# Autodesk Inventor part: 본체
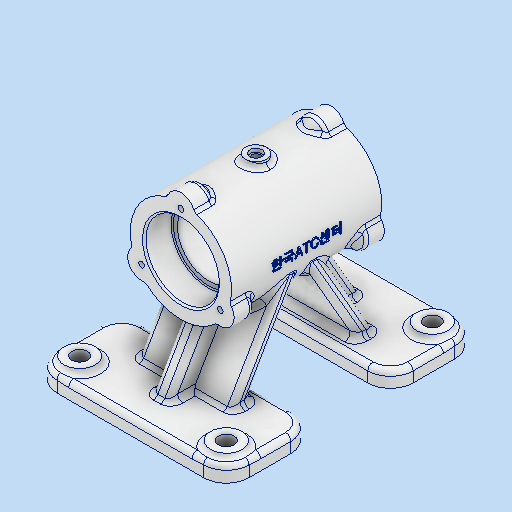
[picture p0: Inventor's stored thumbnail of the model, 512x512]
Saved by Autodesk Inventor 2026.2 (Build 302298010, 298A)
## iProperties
Created: 2026-04
Part Number: 본체
Material: 알루미늄 6061
Document SubType Name: Modeling
Designer: PC-2-06
Mass: 746.295 g
Surface Area: 674.064 cm^2
Volume: 276.405 cm^3
Density: 2.7 g/cm^3
Appearance: 알루미늄 - 평지
Author: PC-2-06
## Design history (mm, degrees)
sketch "스케치1"
  geometry: C1 r 29 at (0, 0); 1 further point
  constraints: 1 centre point, 1 coincident
  dimensions: "d0" = 58 diameter of C1
extrude "돌출1" new body sketch "스케치1" stored distance "d1" = 86; taper "d2" = 0 deg
sketch "스케치2" dims "d3" = 52
  geometry: L1 (0, 41.8)-(0, -40.8) reference; L2 (-40.6, 0)-(40.6, 0) reference; C1 r 8 at (0, 26); C2 r 8 at (-22.517, -13); C3 r 8 at (22.517, -13); 2 further points
  constraints: 3 centre point, 1 coincident, 1 point on line, 1 vertical alignment, 9 other
  dimensions: "d4" = 16 diameter of C1; "d7" = 360 deg dimension on point (0, 0) C1.centre (derived)
extrude "돌출2" join sketch "스케치2" distance "d9" = 10; taper "d10" = 0 deg
sketch "스케치3" dims "d11" = 52
  geometry: L1 (-42.723, 0)-(42.723, 0) reference; L2 (0, -41.6)-(0, 46.6) reference; 5 further points
  constraints: 1 coincident, 1 point on line, 1 vertical alignment, 6 other
  dimensions: "d14" = 360 deg dimension on point (0, 0) point (0, 26) (derived)
hole "구멍1" sketch "스케치3" at (0, 26), (-22.517, -13), (22.517, -13) diameter "d16" = 3.242; stored, may be unused: countersink angle "d20" = 90 deg, drill point angle "d22" = 118 deg; dims "d17" = 8, "d18" = 4, "d19" = 2, "d21" = 10
node "작업 평면1"
sketch "스케치4"
  geometry: L1 (55, 72)-(-55, 72); L2 (-55, 72)-(-55, 22); L3 (-55, 22)-(55, 22); L4 (55, 22)-(55, 72); L5 (55, -22)-(-55, -22); L6 (-55, -22)-(-55, -72); L7 (-55, -72)-(55, -72); L8 (55, -72)-(55, -22); L9 (0, -127.783)-(0, 129.949) reference; L10 (-81.651, 0)-(69.198, 0) reference; 1 further point
  constraints: 16 end point, 4 parallel, 2 horizontal, 2 perpendicular, 1 point on line, 3 other
  dimensions: "d24" = 144 distance between parallel lines of L7 L1; "d25" = 110 distance of L1.start L1.end; "d26" = 50 distance of L3.end L1.start; "d27" = 44 distance of L5.end L2.end
extrude "돌출3" join sketch "스케치4" distance "d28" = 9; taper "d29" = 0 deg
fillet "모깎기1" dims "d30" = 13
sketch "스케치5"
  geometry: C1 r 9 at (-42, -59); C2 r 9 at (42, -59); A1 r 13 centre (-42, -59) between (-55, -59) and (-42, -72) reference; A2 r 13 centre (42, -59) between (42, -72) and (55, -59) reference; 1 further point
  constraints: 2 centre point, 2 coincident
  dimensions: "d31" = 18 diameter of C1; "d33" = 18 diameter of C2
extrude "돌출5" join sketch "스케치5" distance "d41" = 3; taper "d42" = 0 deg
sketch "스케치7"
  geometry: C1 r 9 at (0, 0) reference; C2 r 9 at (84, 0) reference; C3 r 4.5 at (0, 0); C4 r 4.5 at (84, 0); 1 further point
  constraints: 2 centre point, 2 coincident
  dimensions: "d43" = 9 diameter of C3; "d44" = 9 diameter of C4
extrude "돌출6" cut sketch "스케치7" extent not by distance; stored distance "d45" = 0; taper "d46" = 0 deg
sketch "스케치8"
  geometry: L1 (-29, -43)-(-29, 43) reference; L2 (27.942, 43)-(-7.25, 43) reference; L3 (-72, 59)-(-72, 35) reference; L4 (-72, 22)-(-72, 35) reference; L5 (-63, 35)-(-63, 22) reference; L6 (-63, 59)-(-63, 35) reference; L7 (-63, -59)-(-63, -35) reference; L8 (-63, -22)-(-63, -35) reference; L9 (-60, -50)-(-60, -68) reference; L10 (-63, -50)-(-63, -68) reference; L11 (-72, -59)-(-72, -35) reference; L12 (-72, -22)-(-63, -22) reference; L13 (-63, 32)-(-7.574, 0); L14 (-7.574, 0)-(-63, -32); L15 (-93.2, 0)-(55.2, 0) reference; L16 (-67.431, 43.796)-(0, 4.865); L17 (0, -4.865)-(-67.337, -43.742); L18 (0, 100.8)-(0, -100.8) reference; L19 (0, 4.865)-(0, -4.865); 3 further points
  constraints: 10 end point, 5 point on line, 2 parallel, 1 collinear, 1 other
  dimensions: "d48" = 10 distance of L5.end L13.start; "d49" = 60 deg angle of L14 L13; "d50" = 8 distance between parallel lines of L13 L16; "d51" = 8 distance between parallel lines of L14 L17
extrude "돌출7" join sketch "스케치8" stored distance "d52" = 54; taper "d53" = 0 deg
sketch "스케치9"
  geometry: L1 (-10.583, 10.975)-(-63, 41.238) reference; L2 (-10.583, -10.975)-(-63, -41.238) reference; L3 (-10.583, 1.737)-(-63, 32) reference; L4 (0, 18.721)-(-63, 55.094); L5 (-63, 68)-(-63, 50) reference; L6 (-63, 35)-(-63, 59) reference; L7 (0, 4.865)-(-63, 41.238); L8 (0, 100.8)-(0, -100.8) reference; 2 further points
  constraints: 4 end point, 4 point on line, 2 parallel
  dimensions: "d54" = 12 distance between parallel lines of L1 L4; "d55" = 12 distance between parallel lines of L4 L7
extrude "돌출8" join sketch "스케치9" stored distance "d56" = 10; taper "d57" = 0 deg
sketch "스케치10"
  geometry: L1 (0, 100.8)-(0, -100.8) reference; L2 (-93.2, 0)-(55.2, 0) reference; L3 (0, 43)-(21, 43); L4 (21, 43)-(21, 27.6); L5 (20.4, 27)-(0, 27); L6 (0, 27)-(0, 43); L7 (27.942, 43)-(-7.25, 43) reference; L8 (0, 27)-(18, 27); L9 (18, 27)-(18, -27); L10 (18, -27)-(0, -27); L11 (0, -27)-(0, 27); L12 (0, -43)-(21, -43); L13 (21, -43)-(21, -27.6); L14 (20.4, -27)-(0, -27); A1 r 0.6 centre (20.4, 27.6) between (20.4, 27) and (21, 27.6); A2 r 0.6 centre (20.4, -27.6) between (21, -27.6) and (20.4, -27); 6 further points
  constraints: 22 end point, 6 point on line, 4 parallel, 4 point on circle, 4 tangent, 3 symmetric about line, 2 centre point, 2 horizontal, 2 perpendicular, 1 equal radius
  dimensions: "d58" = 21 distance of point (21, 27) L5.end; "d59" = 16 distance of L3.end point (21, 27); "d60" = 18 distance of L9.end L10.end; "d61" = 54 distance of L8.end L9.end; "d62" = 0.6 radius of A1 (derived)
revolve "회전1" sketch "스케치10" stored, may be unused: angle "d63" = 90 deg
chamfer "모따기1" distance "d64" = 1; stored, may be unused: second distance "d65" = 2, angle "d66" = 45 deg
sketch "스케치11"
  geometry: L1 (34, 33)-(1, 0); L2 (1, 0)-(34, -33); L3 (0, 100.8)-(0, -100.8) reference; L4 (-98.48, 0)-(86.879, 0) reference; L5 (27.942, 33)-(34, 33) reference; L6 (34, 43)-(34, 33) reference; L7 (27.942, -33)-(34, -33) reference; L8 (34, -33)-(34, -43) reference; L9 (24.379, 43)-(27.621, 43) reference; L10 (26, 43)-(26, -43); L11 (27.621, -43)-(24.379, -43) reference; L12 (34, -33)-(26, -33); L13 (34, 33)-(26, 33); 5 further points
  constraints: 10 end point, 4 point on line, 2 midpoint, 1 perpendicular, 1 other
  dimensions: "d67" = 90 deg angle of L2 L1
revolve "회전2" sketch "스케치11" stored, may be unused: angle "d68" = 180 deg
node "작업 평면2"
sketch "스케치12"
  geometry: C1 r 6 at (0, 0); 1 further point
  constraints: 1 centre point, 1 coincident
  dimensions: "d73" = 12 diameter of C1
extrude "돌출9" join sketch "스케치12" stored distance "d74" = 10; taper "d75" = 0 deg
sketch "스케치13"
  geometry: 2 further points
  constraints: 1 coincident
hole "구멍2" sketch "스케치13" at (0, 0) diameter "d76" = 4.917; stored, may be unused: countersink angle "d80" = 90 deg, drill point angle "d82" = 118 deg; dims "d77" = 15, "d78" = 7, "d79" = 2, "d81" = 17.1
fillet "모깎기2" dims "d83" = 3
fillet "모깎기3" dims "d84" = 3
fillet "모깎기4" dims "d85" = 3
fillet "모깎기5" dims "d86" = 3
fillet "모깎기6" dims "d87" = 3
fillet "모깎기7" dims "d88" = 3
fillet "모깎기8" dims "d89" = 3
node "작업 평면3"
sketch "스케치14"
  geometry: L1 (-72, -72)-(-72, -59) reference; 2 further points
  constraints: 1 other
  dimensions: "d91" = 0 distance of point (0, 0) point (0, 0); "d92" = 72 distance from line of L1 point (0, 0)
feature "엠보싱1" sketch "스케치14" dims "d93" = 0.5, "d94" = 0
feature "ԯ耀Ա耀Գ耀Ե耀Է耀Թ耀Ի耀Խ耀" dims "d0" = 58, "d1" = 86, "d2" = 0, "d3" = 52, "d4" = 16, "d5" = 30, "d7" = 360 deg (derived), "d9" = 10, "d10" = 0, "d11" = 52, "d12" = 30, "d14" = 360 deg (derived), "d16" = 3.242, "d17" = 8, "d18" = 4, "d19" = 2, "d20" = 90 deg, "d21" = 10, "d22" = 118 deg, "d23" = -72, "d24" = 144, "d25" = 110, "d26" = 50, "d27" = 44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
node "솔리드1"
mirror "미러1"
mirror "미러2"
mirror "미러3"
pattern_circular "원형 패턴1" dims angle "d70" = 360 deg
mirror "미러4"
node "스케치 - 원형 패턴1" dims "d7" = 360 deg (derived)
node "스케치 - 원형 패턴2" dims "d14" = 360 deg (derived)
feature "A9D066F2-1C7D-4E18-AEED-F7BC21143FA4" dims "d16" = 3.242, "d17" = 8, "d18" = 4, "d19" = 2, "d20" = 90 deg, "d21" = 10, "d22" = 118 deg
